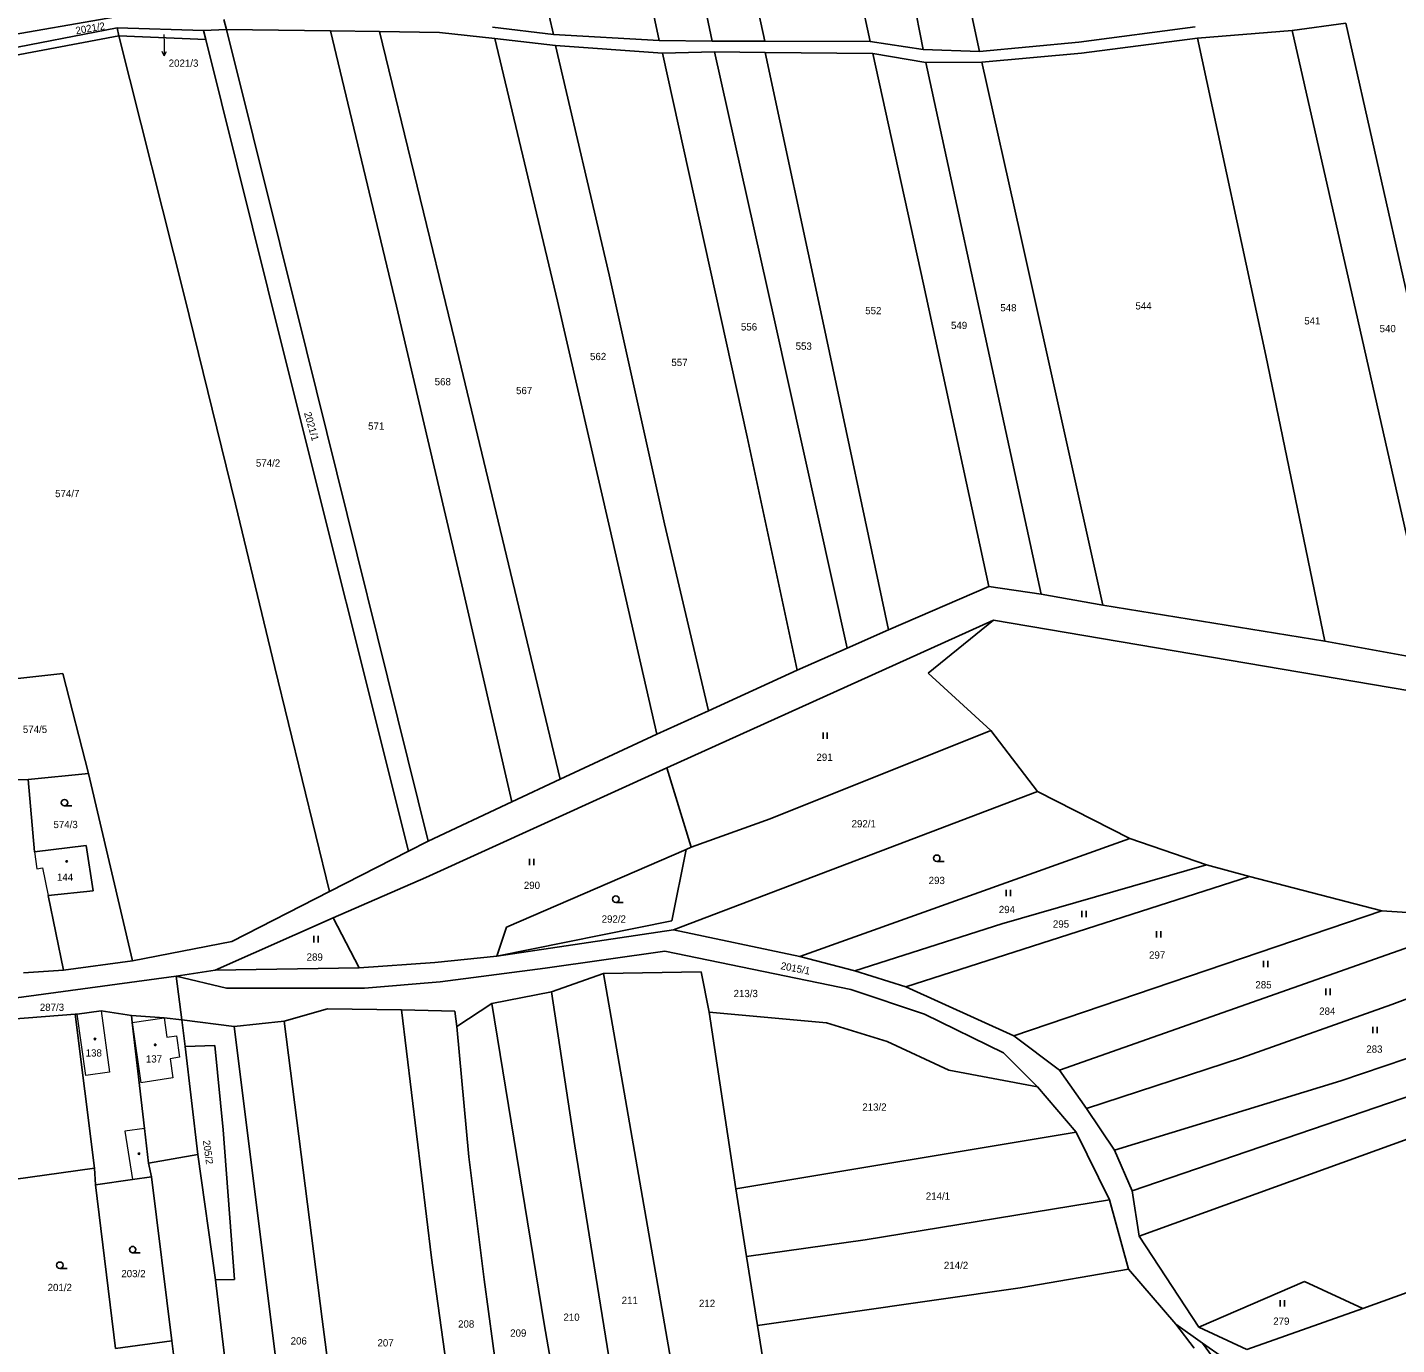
# Model space of a CAD drawing. Extents: x -820420 to -815896, y -1105820 to -1103643.
# Drawn here: x -817372.7 to -817052, y -1104919.6 to -1104611.1 of the extents above; entities that cross this region are included whole.
import ezdxf
from ezdxf.enums import TextEntityAlignment as Align

# ---------------------------------------------------------------- set-up
doc = ezdxf.new("R2010")
doc.units = 0
doc.header["$LTSCALE"] = 0.68
for name, color, linetype, lineweight in [('1', 7, 'Continuous', 25), ('3', 7, 'Continuous', 25), ('4', 7, 'Continuous', 13), ('5', 7, 'Continuous', 25), ('7', 7, 'Continuous', 13)]:
    doc.layers.add(name, color=color, linetype=linetype, lineweight=lineweight)
doc.layers.add('2', color=7, linetype='Continuous')

msp = doc.modelspace()

# ---------------------------------------------------------------- linework, layer by layer
at = {"layer": '1'}
for p, q in [((-817249.48, -1104612.75), (-817265.19, -1104544.57)), ((-817173.99, -1104560.42), (-817162.88, -1104616.27)), ((-817211.16, -1104562.86), (-817200.01, -1104614.36)), ((-817175.36, -1104614.37), (-817186.11, -1104563.1)), ((-817234.84, -1104566.91), (-817224.73, -1104614.15)), ((-817212.34, -1104614.33), (-817220.93, -1104572.93)), ((-817383.44, -1104614.12), (-817352.01, -1104608.6)), ((-817382.75, -1104617.18), (-817351.68, -1104611.19)), ((-817351.68, -1104611.19), (-817351.25, -1104613.05)), ((-817351.68, -1104611.19), (-817331.48, -1104611.86)), ((-817331.48, -1104611.86), (-817326.09, -1104611.63)), ((-817330.9, -1104613.9), (-817331.48, -1104611.86)), ((-817326.67, -1104609.29), (-817326.09, -1104611.63)), ((-817301.74, -1104611.92), (-817326.09, -1104611.63)), ((-817326.09, -1104611.63), (-817307.33, -1104686.74)), ((-817290.24, -1104612.08), (-817301.74, -1104611.92)), ((-817301.74, -1104611.92), (-817286.27, -1104676.35)), ((-817276.17, -1104612.28), (-817290.24, -1104612.08)), ((-817290.24, -1104612.08), (-817272.59, -1104684.49)), ((-817263.79, -1104611.01), (-817249.48, -1104612.75)), ((-817099.21, -1104611), (-817126.48, -1104614.59)), ((-817076.46, -1104611.84), (-817098.69, -1104613.59)), ((-817062.06, -1104675.48), (-817076.46, -1104611.84)), ((-817351.25, -1104613.05), (-817383.47, -1104619.16)), ((-817351.25, -1104613.05), (-817335.88, -1104674.12)), ((-817330.9, -1104613.9), (-817351.25, -1104613.05)), ((-817312.76, -1104687.07), (-817330.9, -1104613.9)), ((-817263.23, -1104613.72), (-817276.17, -1104612.28)), ((-817249.04, -1104615.31), (-817263.23, -1104613.72)), ((-817263.23, -1104613.72), (-817248.55, -1104675.22)), ((-817249.48, -1104612.75), (-817224.73, -1104614.15)), ((-817224.73, -1104614.15), (-817212.34, -1104614.33)), ((-817200.01, -1104614.36), (-817212.34, -1104614.33)), ((-817200.01, -1104614.36), (-817175.36, -1104614.37)), ((-817162.88, -1104616.27), (-817175.36, -1104614.37)), ((-817098.69, -1104613.59), (-817125.83, -1104617.13)), ((-817098.69, -1104613.59), (-817082.69, -1104687.93)), ((-817224, -1104617.14), (-817249.04, -1104615.31)), ((-817236.44, -1104669.05), (-817249.04, -1104615.31)), ((-817211.78, -1104616.79), (-817224, -1104617.14)), ((-817224, -1104617.14), (-817204.12, -1104706.98)), ((-817199.89, -1104617.01), (-817211.78, -1104616.79)), ((-817211.78, -1104616.79), (-817197.81, -1104679.35)), ((-817174.71, -1104617.18), (-817199.89, -1104617.01)), ((-817199.89, -1104617.01), (-817186.4, -1104679.92)), ((-817174.71, -1104617.18), (-817162.25, -1104619.35)), ((-817162.87, -1104671.23), (-817174.71, -1104617.18)), ((-817162.88, -1104616.27), (-817149.71, -1104616.75)), ((-817125.83, -1104617.13), (-817149.14, -1104619.27)), ((-817149.14, -1104619.27), (-817162.25, -1104619.35)), ((-817162.25, -1104619.35), (-817143.93, -1104703.96)), ((-817140.16, -1104659.37), (-817149.14, -1104619.27)), ((-817120.8, -1104746.41), (-817140.16, -1104659.37)), ((-817223.49, -1104727.39), (-817236.44, -1104669.05)), ((-817147.5, -1104742), (-817162.87, -1104671.23)), ((-817335.88, -1104674.12), (-817323.93, -1104722.78)), ((-817248.55, -1104675.22), (-817236.28, -1104728.47)), ((-817043.08, -1104759.53), (-817062.06, -1104675.48)), ((-817286.27, -1104676.35), (-817270.92, -1104741.67)), ((-817197.81, -1104679.35), (-817180.69, -1104756.51)), ((-817186.4, -1104679.92), (-817171.03, -1104752.2)), ((-817247.91, -1104787.17), (-817272.59, -1104684.49)), ((-817283.43, -1104803.99), (-817312.76, -1104687.07)), ((-817307.33, -1104686.74), (-817278.87, -1104801.64)), ((-817082.69, -1104687.93), (-817068.88, -1104754.87)), ((-817143.93, -1104703.96), (-817135.26, -1104743.84)), ((-817204.12, -1104706.98), (-817192.43, -1104761.66)), ((-817323.93, -1104722.78), (-817314.75, -1104761.01)), ((-817213.2, -1104771.15), (-817223.49, -1104727.39)), ((-817225.31, -1104776.6), (-817236.28, -1104728.47)), ((-817270.92, -1104741.67), (-817259.27, -1104792.48)), ((-817147.5, -1104742), (-817171.03, -1104752.2)), ((-817135.26, -1104743.84), (-817147.5, -1104742)), ((-817120.8, -1104746.41), (-817135.26, -1104743.84)), ((-817068.88, -1104754.87), (-817120.8, -1104746.41)), ((-817222.95, -1104784.51), (-817146.47, -1104749.9)), ((-817146.47, -1104749.9), (-817161.77, -1104762.33)), ((-817146.47, -1104749.9), (-817013.14, -1104772.55)), ((-817171.03, -1104752.2), (-817180.69, -1104756.51)), ((-817043.08, -1104759.53), (-817068.88, -1104754.87)), ((-817180.69, -1104756.51), (-817192.43, -1104761.66)), ((-817364.44, -1104762.43), (-817381.81, -1104764.35)), ((-817358.36, -1104785.8), (-817364.44, -1104762.43)), ((-817314.75, -1104761.01), (-817301.94, -1104813.5)), ((-817192.43, -1104761.66), (-817213.2, -1104771.15)), ((-817161.77, -1104762.33), (-817147.09, -1104775.76)), ((-817213.2, -1104771.15), (-817225.31, -1104776.6)), ((-817247.91, -1104787.17), (-817225.31, -1104776.6)), ((-817147.09, -1104775.76), (-817198.78, -1104796.48)), ((-817147.09, -1104775.76), (-817136.14, -1104790.04)), ((-817279.36, -1104810.2), (-817222.95, -1104784.51)), ((-817222.95, -1104784.51), (-817217.21, -1104803.12)), ((-817378.64, -1104787.35), (-817372.56, -1104787.23)), ((-817372.56, -1104787.23), (-817358.36, -1104785.8)), ((-817358.36, -1104785.8), (-817348.06, -1104829.74)), ((-817247.91, -1104787.17), (-817259.27, -1104792.48)), ((-817136.14, -1104790.04), (-817221.38, -1104822.43)), ((-817136.14, -1104790.04), (-817114.51, -1104801.06)), ((-817259.27, -1104792.48), (-817278.87, -1104801.64)), ((-817198.78, -1104796.48), (-817217.21, -1104803.12)), ((-817114.51, -1104801.06), (-817191.81, -1104828.67)), ((-817114.51, -1104801.06), (-817096.59, -1104807.22)), ((-817358.92, -1104802.72), (-817357.31, -1104813.34)), ((-817283.43, -1104803.99), (-817301.94, -1104813.5)), ((-817278.87, -1104801.64), (-817283.43, -1104803.99)), ((-817260.47, -1104821.84), (-817218.38, -1104803.63)), ((-817218.38, -1104803.63), (-817221.75, -1104820.3)), ((-817218.38, -1104803.63), (-817217.21, -1104803.12)), ((-817144.46, -1104821.07), (-817096.59, -1104807.22)), ((-817096.59, -1104807.22), (-817086.46, -1104809.97)), ((-817301.07, -1104819.65), (-817279.36, -1104810.2)), ((-817086.46, -1104809.97), (-817166.98, -1104835.77)), ((-817086.46, -1104809.97), (-817055.48, -1104818)), ((-817357.31, -1104813.34), (-817367.86, -1104814.39)), ((-817301.94, -1104813.5), (-817324.83, -1104825.19)), ((-817367.86, -1104814.39), (-817364.21, -1104831.92)), ((-817328.69, -1104831.88), (-817301.07, -1104819.65)), ((-817294.97, -1104831.33), (-817301.07, -1104819.65)), ((-817262.79, -1104828.6), (-817221.75, -1104820.3)), ((-817055.48, -1104818), (-817141.67, -1104847.25)), ((-817029.97, -1104819.74), (-817131.01, -1104855.32)), ((-817055.48, -1104818), (-817029.97, -1104819.74)), ((-817260.47, -1104821.84), (-817262.79, -1104828.6)), ((-817221.38, -1104822.43), (-817262.79, -1104828.6)), ((-817191.81, -1104828.67), (-817221.38, -1104822.43)), ((-817178.93, -1104832.05), (-817144.46, -1104821.07)), ((-817053.19, -1104839.93), (-817007.02, -1104822.84)), ((-817324.83, -1104825.19), (-817348.06, -1104829.74)), ((-817348.06, -1104829.74), (-817364.21, -1104831.92)), ((-817277.26, -1104830.13), (-817294.97, -1104831.33)), ((-817262.79, -1104828.6), (-817277.26, -1104830.13)), ((-817223.45, -1104827.46), (-817251.47, -1104831.44)), ((-817223.45, -1104827.46), (-817179.83, -1104836.43)), ((-817178.93, -1104832.05), (-817191.81, -1104828.67)), ((-817384.22, -1104839.61), (-817337.83, -1104833.32)), ((-817364.21, -1104831.92), (-817373.63, -1104832.48)), ((-817337.83, -1104833.32), (-817328.69, -1104831.88)), ((-817326.05, -1104836.07), (-817337.83, -1104833.32)), ((-817337.83, -1104833.32), (-817336.5, -1104843.53)), ((-817328.69, -1104831.88), (-817294.97, -1104831.33)), ((-817251.47, -1104831.44), (-817276.04, -1104834.62)), ((-817237.78, -1104832.63), (-817249.94, -1104836.97)), ((-817214.94, -1104832.3), (-817237.78, -1104832.63)), ((-817237.78, -1104832.63), (-817219.14, -1104939.69)), ((-817214.94, -1104832.3), (-817213.07, -1104841.69)), ((-817166.98, -1104835.77), (-817178.93, -1104832.05)), ((-817293.73, -1104836.1), (-817326.05, -1104836.07)), ((-817276.04, -1104834.62), (-817293.73, -1104836.1)), ((-817179.83, -1104836.43), (-817162.63, -1104842.19)), ((-817141.67, -1104847.25), (-817166.98, -1104835.77)), ((-817263.93, -1104839.71), (-817272.12, -1104845.1)), ((-817249.94, -1104836.97), (-817263.93, -1104839.71)), ((-817263.93, -1104839.71), (-817251.64, -1104914.68)), ((-817244.53, -1104873.02), (-817249.94, -1104836.97)), ((-817376.39, -1104843.4), (-817361.55, -1104842.2)), ((-817361.55, -1104842.2), (-817361.02, -1104842.19)), ((-817361.55, -1104842.2), (-817356.98, -1104878.24)), ((-817361.02, -1104842.19), (-817355.45, -1104841.39)), ((-817355.45, -1104841.39), (-817348.34, -1104842.53)), ((-817348.34, -1104842.53), (-817340.67, -1104843.03)), ((-817348.2, -1104844.13), (-817348.34, -1104842.53)), ((-817302.4, -1104840.92), (-817312.54, -1104843.82)), ((-817285.12, -1104841.16), (-817302.4, -1104840.92)), ((-817278.03, -1104899.26), (-817285.12, -1104841.16)), ((-817285.12, -1104841.16), (-817272.62, -1104841.5)), ((-817272.12, -1104845.1), (-817272.62, -1104841.5)), ((-817185.59, -1104844.19), (-817213.07, -1104841.69)), ((-817213.07, -1104841.69), (-817206.75, -1104883.1)), ((-817162.63, -1104842.19), (-817144.11, -1104851.24)), ((-817112.29, -1104894.16), (-816970.47, -1104842.9)), ((-817088.37, -1104852.43), (-817053.19, -1104839.93)), ((-817348.2, -1104844.13), (-817345.3, -1104868.94)), ((-817340.67, -1104843.03), (-817336.5, -1104843.53)), ((-817324.28, -1104845.05), (-817336.5, -1104843.53)), ((-817336.5, -1104843.53), (-817335.73, -1104849.73)), ((-817324.28, -1104845.05), (-817312.54, -1104843.82)), ((-817313.7, -1104929.43), (-817324.28, -1104845.05)), ((-817312.54, -1104843.82), (-817303.68, -1104913.59)), ((-817269.34, -1104875.63), (-817272.12, -1104845.1)), ((-817171.35, -1104848.61), (-817185.59, -1104844.19)), ((-817156.89, -1104855.29), (-817171.35, -1104848.61)), ((-817131.01, -1104855.32), (-817141.67, -1104847.25)), ((-817033.21, -1104847.02), (-817065.09, -1104857.79)), ((-817335.73, -1104849.73), (-817328.78, -1104849.54)), ((-817335.73, -1104849.73), (-817332.8, -1104875.06)), ((-817328.78, -1104849.54), (-817326.89, -1104869.3)), ((-817144.11, -1104851.24), (-817136.14, -1104859.21)), ((-817124.64, -1104864.28), (-817088.37, -1104852.43)), ((-817136.14, -1104859.21), (-817156.89, -1104855.29)), ((-817124.64, -1104864.28), (-817131.01, -1104855.32)), ((-817065.09, -1104857.79), (-817118.07, -1104874.04)), ((-817113.99, -1104883.6), (-817041.18, -1104858.69)), ((-817136.14, -1104859.21), (-817127.08, -1104869.86)), ((-817118.07, -1104874.04), (-817124.64, -1104864.28)), ((-816939.91, -1104867.38), (-817059.91, -1104911.14)), ((-817344.32, -1104877.05), (-817345.3, -1104868.94)), ((-817326.89, -1104869.3), (-817324.16, -1104904.3)), ((-817206.75, -1104883.1), (-817127.08, -1104869.86)), ((-817127.08, -1104869.86), (-817119.24, -1104885.67)), ((-817235.75, -1104927.46), (-817244.53, -1104873.02)), ((-817113.99, -1104883.6), (-817118.07, -1104874.04)), ((-817380.49, -1104881.55), (-817356.98, -1104878.24)), ((-817356.98, -1104878.24), (-817356.77, -1104882.14)), ((-817344.32, -1104877.05), (-817332.8, -1104875.06)), ((-817344.32, -1104877.05), (-817343.64, -1104880.25)), ((-817332.8, -1104875.06), (-817328.67, -1104904.4)), ((-817265.75, -1104904.36), (-817269.34, -1104875.63)), ((-817356.77, -1104882.14), (-817348.11, -1104880.89)), ((-817348.11, -1104880.89), (-817343.64, -1104880.25)), ((-817343.64, -1104880.25), (-817338.91, -1104918.67)), ((-817356.77, -1104882.14), (-817352.04, -1104920.46)), ((-817206.75, -1104883.1), (-817204.25, -1104898.92)), ((-817112.29, -1104894.16), (-817113.99, -1104883.6)), ((-817176.5, -1104895.03), (-817119.24, -1104885.67)), ((-817119.24, -1104885.67), (-817114.86, -1104901.9)), ((-817098.38, -1104915.53), (-817112.29, -1104894.16)), ((-817204.25, -1104898.92), (-817176.5, -1104895.03)), ((-817270.42, -1104954.69), (-817278.03, -1104899.26)), ((-817204.25, -1104898.92), (-817201.7, -1104915.13)), ((-817140.22, -1104906.31), (-817114.86, -1104901.9)), ((-817114.86, -1104901.9), (-817103.74, -1104914.79)), ((-817324.16, -1104904.3), (-817328.67, -1104904.4)), ((-817328.67, -1104904.4), (-817324.83, -1104936.23)), ((-817260.57, -1104942.32), (-817265.75, -1104904.36)), ((-817201.7, -1104915.13), (-817140.22, -1104906.31)), ((-817073.63, -1104904.82), (-817098.38, -1104915.53)), ((-817059.91, -1104911.14), (-817073.63, -1104904.82)), ((-817087.12, -1104920.75), (-817059.91, -1104911.14)), ((-817303.68, -1104913.59), (-817296.58, -1104968.84)), ((-817251.64, -1104914.68), (-817248.06, -1104935.25)), ((-817201.7, -1104915.13), (-817198.15, -1104937.62)), ((-817103.74, -1104914.79), (-817099.47, -1104920.4)), ((-817097.46, -1104919.23), (-817103.74, -1104914.79)), ((-817098.38, -1104915.53), (-817087.12, -1104920.75)), ((-817352.04, -1104920.46), (-817338.91, -1104918.67)), ((-817338.91, -1104918.67), (-817329.34, -1104991.82)), ((-817097.46, -1104919.23), (-817081.32, -1104941.24)), ((-817092.57, -1104922.7), (-817097.46, -1104919.23))]:
    msp.add_line(p, q, dxfattribs=at)
for points in [[(-817126.48, -1104614.59), (-817149.71, -1104616.75), (-817167.36, -1104534.36)], [(-817049.39, -1104674.46), (-817063.96, -1104610.15), (-817076.46, -1104611.84)], [(-817372.56, -1104787.23), (-817371.02, -1104804.15), (-817358.92, -1104802.72)]]:
    msp.add_lwpolyline(points, dxfattribs=at)
at = {"layer": '3'}
for p, q in [((-817186.361, -1104777.71), (-817186.361, -1104776.21)), ((-817185.36, -1104777.71), (-817185.36, -1104776.21)), ((-817364.013, -1104793.42), (-817362.263, -1104793.42)), ((-817255.071, -1104807.33), (-817255.071, -1104805.83)), ((-817254.07, -1104807.33), (-817254.07, -1104805.83)), ((-817159.723, -1104806.43), (-817157.973, -1104806.43)), ((-817143.471, -1104814.58), (-817143.471, -1104813.08)), ((-817142.47, -1104814.58), (-817142.47, -1104813.08)), ((-817234.893, -1104816.01), (-817233.143, -1104816.01)), ((-817125.771, -1104819.49), (-817125.771, -1104817.99)), ((-817124.77, -1104819.49), (-817124.77, -1104817.99)), ((-817108.231, -1104824.25), (-817108.231, -1104822.75)), ((-817107.23, -1104824.25), (-817107.23, -1104822.75)), ((-817305.611, -1104825.38), (-817305.611, -1104823.88)), ((-817304.61, -1104825.38), (-817304.61, -1104823.88)), ((-817083.221, -1104831.2), (-817083.221, -1104829.7)), ((-817082.22, -1104831.2), (-817082.22, -1104829.7)), ((-817068.611, -1104837.71), (-817068.611, -1104836.21)), ((-817067.61, -1104837.71), (-817067.61, -1104836.21)), ((-817057.621, -1104846.66), (-817057.621, -1104845.16)), ((-817056.62, -1104846.66), (-817056.62, -1104845.16)), ((-817348.053, -1104898.08), (-817346.303, -1104898.08)), ((-817365.113, -1104901.74), (-817363.363, -1104901.74)), ((-817079.291, -1104910.67), (-817079.291, -1104909.17)), ((-817078.29, -1104910.67), (-817078.29, -1104909.17))]:
    msp.add_line(p, q, dxfattribs=at)
for centre in [(-817364.0129, -1104792.6698), (-817159.7229, -1104805.6798), (-817234.8929, -1104815.2598), (-817348.0529, -1104897.3298), (-817365.1129, -1104900.9898)]:
    msp.add_circle(centre, 0.75, dxfattribs=at)
at = {"layer": '4'}
for p, q in [((-817369.16, -1104807.95), (-817367.86, -1104814.39)), ((-817355.45, -1104841.39), (-817353.44, -1104855.78)), ((-817348.2, -1104844.13), (-817340.67, -1104843.03)), ((-817348.2, -1104844.13), (-817346.12, -1104858.26)), ((-817340.67, -1104843.03), (-817340.02, -1104847.58)), ((-817340.02, -1104847.58), (-817337.75, -1104847.27)), ((-817337.75, -1104847.27), (-817337.06, -1104852.29)), ((-817337.06, -1104852.29), (-817339.27, -1104852.63)), ((-817339.27, -1104852.63), (-817338.63, -1104857.13)), ((-817338.63, -1104857.13), (-817346.12, -1104858.26)), ((-817345.3, -1104868.94), (-817349.87, -1104869.6)), ((-817349.87, -1104869.6), (-817348.11, -1104880.89))]:
    msp.add_line(p, q, dxfattribs=at)
for points in [[(-817371.02, -1104804.15), (-817370.52, -1104808.12), (-817369.16, -1104807.95)], [(-817353.44, -1104855.78), (-817359, -1104856.54), (-817361.02, -1104842.19)]]:
    msp.add_lwpolyline(points, dxfattribs=at)
at = {"layer": '5'}
for centre in [(-817363.4968, -1104806.4292), (-817356.8668, -1104848.0092), (-817342.7668, -1104849.3692), (-817346.5768, -1104874.8692)]:
    msp.add_circle(centre, 0.175, dxfattribs=at)
at = {"layer": '7'}
msp.add_line((-817340.638, -1104617.761), (-817340.154, -1104616.75), dxfattribs=at)
msp.add_lwpolyline([(-817340.74, -1104612.76), (-817340.69, -1104614.76), (-817340.638, -1104617.761), (-817341.156, -1104616.768)], dxfattribs=at)

# ---------------------------------------------------------------- texts
at = {"layer": '2'}
for s, rotation, p in [('2021/2', 10, (-817357.8401, -1104612.1348)), ('2021/1', 286, (-817306.9744, -1104704.7762)), ('2015/1', 349, (-817192.9877, -1104832.2925)), ('205/2', 278, (-817331.2318, -1104874.6387))]:
    msp.add_text(s, height=1.7, rotation=rotation, dxfattribs=at).set_placement(p, align=Align.CENTER)
msp.add_text('2021/3', height=1.7, dxfattribs=at).set_placement((-817339.61, -1104620.325))
for s, p in [('548', (-817142.949, -1104677.605)), ('544', (-817111.299, -1104677.165)), ('552', (-817174.589, -1104678.275)), ('541', (-817071.769, -1104680.675)), ('556', (-817203.699, -1104682.085)), ('549', (-817154.499, -1104681.745)), ('540', (-817054.119, -1104682.485)), ('553', (-817190.879, -1104686.595)), ('562', (-817239.039, -1104689.025)), ('557', (-817219.979, -1104690.405)), ('568', (-817275.419, -1104694.915)), ('567', (-817256.359, -1104696.995)), ('571', (-817291.009, -1104705.315)), ('574/2', (-817316.34, -1104713.965)), ('574/7', (-817363.36, -1104721.115)), ('574/5', (-817370.92, -1104776.335)), ('291', (-817186.009, -1104782.865)), ('574/3', (-817363.75, -1104798.625)), ('292/1', (-817176.83, -1104798.435)), ('144', (-817363.889, -1104810.965)), ('293', (-817159.729, -1104811.725)), ('290', (-817254.539, -1104812.865)), ('294', (-817143.299, -1104818.525)), ('292/2', (-817235.36, -1104820.755)), ('295', (-817130.629, -1104821.925)), ('289', (-817305.409, -1104829.665)), ('297', (-817108.119, -1104829.185)), ('213/3', (-817204.47, -1104838.205)), ('285', (-817083.209, -1104836.165)), ('287/3', (-817366.95, -1104841.425)), ('284', (-817068.269, -1104842.335)), ('138', (-817357.159, -1104852.115)), ('137', (-817343.059, -1104853.515)), ('283', (-817057.239, -1104851.225)), ('213/2', (-817174.32, -1104864.805)), ('214/1', (-817159.45, -1104885.645)), ('214/2', (-817155.21, -1104901.865)), ('203/2', (-817347.86, -1104903.795)), ('201/2', (-817365.12, -1104907.045)), ('211', (-817231.629, -1104910.065)), ('212', (-817213.519, -1104910.765)), ('210', (-817245.269, -1104914.005)), ('279', (-817079.029, -1104914.935)), ('208', (-817269.939, -1104915.595)), ('209', (-817257.739, -1104917.715)), ('206', (-817309.149, -1104919.555)), ('207', (-817288.819, -1104920.015))]:
    msp.add_text(s, height=1.7, dxfattribs=at).set_placement(p, align=Align.CENTER)

doc.saveas('drawing.dxf')
